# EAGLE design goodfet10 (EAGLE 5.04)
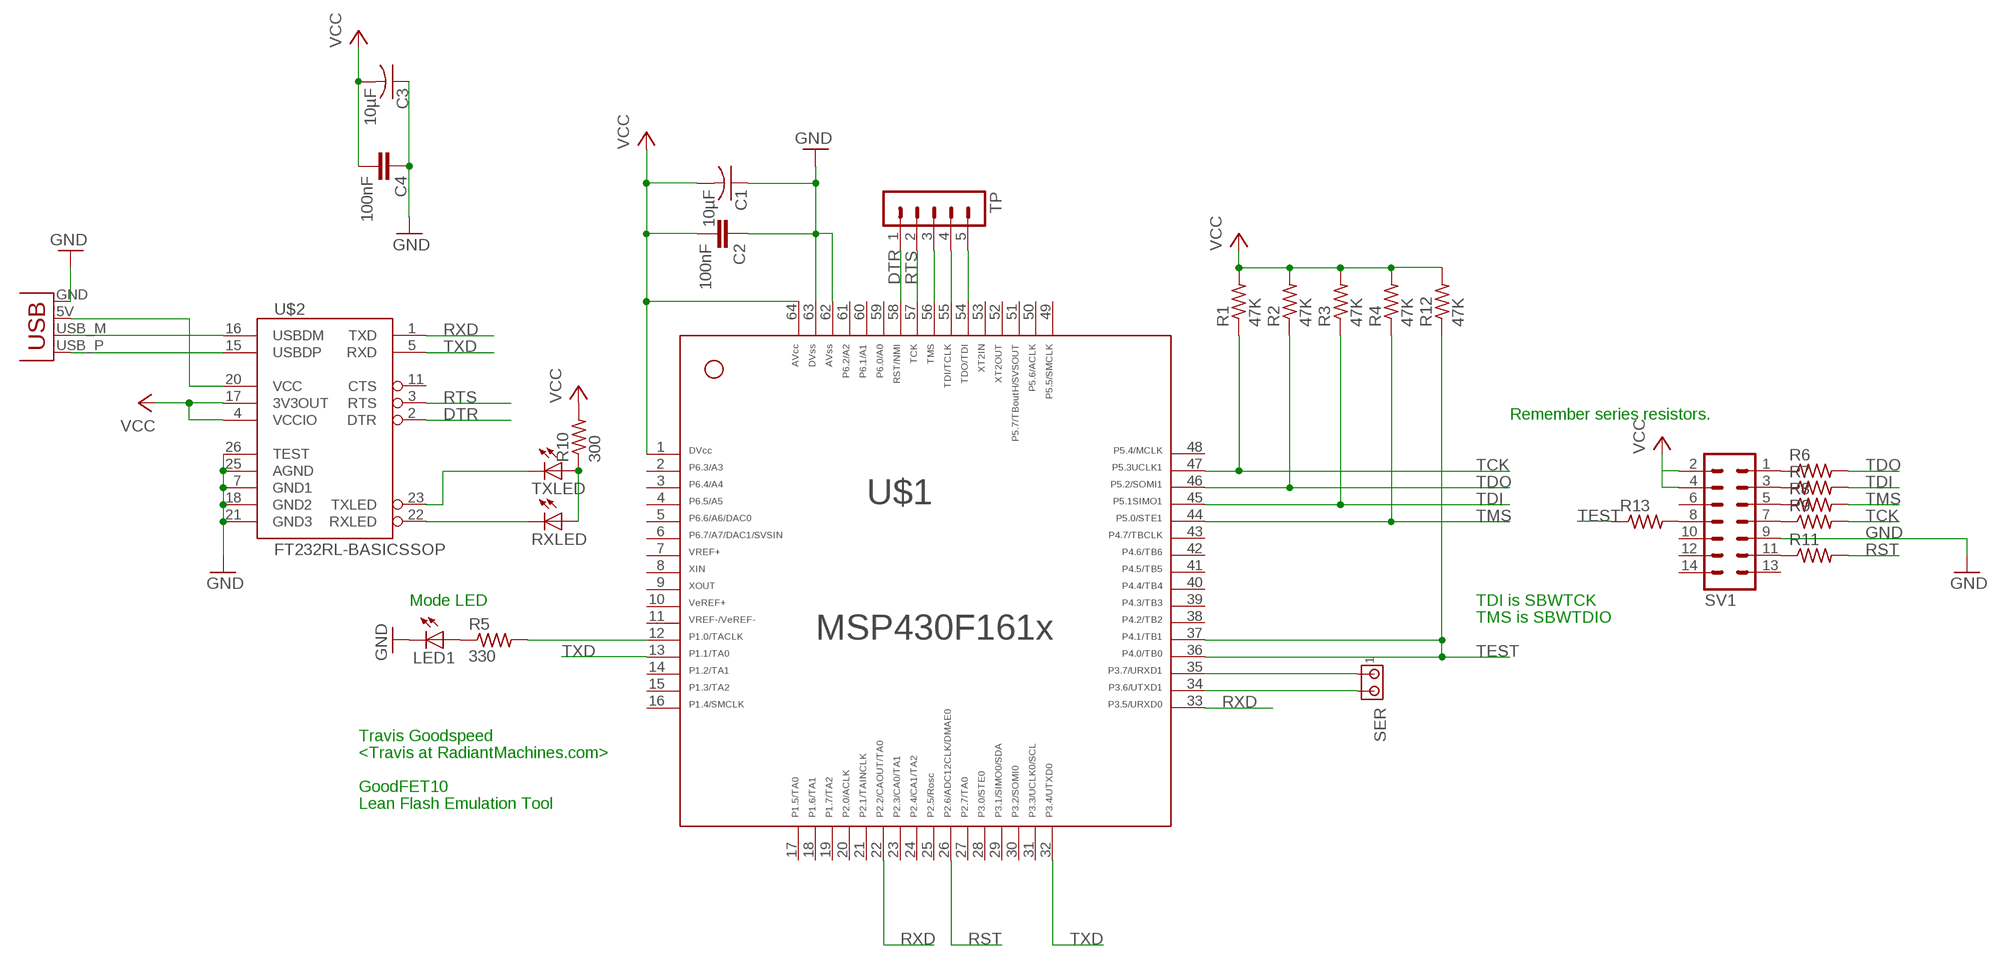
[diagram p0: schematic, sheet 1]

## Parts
C1  10µF  C-USC0603  [C0603]
C2  100nF  C-EUC0603  [C0603]
C3  10µF  C-USC0603  [C0603]
C4  100nF  C-EUC0603  [C0603]
LED1  LEDCHIP-LED0603  [CHIP-LED0603]
R1  47K  R-US_R0603  [R0603]
R2  47K  R-US_R0603  [R0603]
R3  47K  R-US_R0603  [R0603]
R4  47K  R-US_R0603  [R0603]
R5  330  R-US_R0603  [R0603]
R6  R-US_R0603  [R0603]
R7  R-US_R0603  [R0603]
R8  R-US_R0603  [R0603]
R9  R-US_R0603  [R0603]
R10  300  R-US_R0603  [R0603]
R11  R-US_R0603  [R0603]
R12  47K  R-US_R0603  [R0603]
R13  R-US_R0603  [R0603]
RXLED  LEDCHIP-LED0603  [CHIP-LED0603]
SER  MTA02-100  [10X02MTA]
SV1  MA07-2  [MA07-2]
TP  MA05-1  [MA05-1]
TXLED  LEDCHIP-LED0603  [CHIP-LED0603]
U$1  F161X---PM64  [PM/PAG64]
U$2  FT232RL-BASICSSOP  [SSOP28DB]
X1  USBPCB  [USB-A-PCB]

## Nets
DTR: TP.1 U$1.58 U$2.2(DTR)
GND: C1.1 C2.1 C3.1 C4.1 LED1.C SV1.9 U$1.62 U$1.63 U$2.7(GND1) U$2.18(GND2) U$2.21(GND3) U$2.25(AGND) U$2.26(TEST) X1.GND
N$1: R5.2 U$1.12
N$2: LED1.A R5.1
N$3: U$2.15(USBDP) X1.USB_P(D+)
N$4: U$2.16(USBDM) X1.USB_M(D-)
N$5: U$2.20(VCC) X1.5V(VBUS)
N$6: RXLED.C U$2.22(RXLED)
N$7: TXLED.C U$2.23(TXLED)
N$8: R10.1 RXLED.A TXLED.A
N$9: SER.1 U$1.35
N$10: SER.2 U$1.34
N$11: TP.3 U$1.56
N$12: TP.4 U$1.55
N$13: TP.5 U$1.54
N$14: R6.1 SV1.1
N$15: R7.1 SV1.3
N$16: R8.1 SV1.5
N$17: R9.1 SV1.7
N$18: R11.1 SV1.11
N$19: R13.2 SV1.8
RST: R11.2 U$1.26
RTS: TP.2 U$1.57 U$2.3(RTS)
RXD: U$1.22 U$1.33 U$2.1(TXD)
TCK: R1.1 R9.2 U$1.47
TDI: R3.1 R7.2 U$1.45
TDO: R2.1 R6.2 U$1.46
TEST: R12.1 R13.1 U$1.36 U$1.37
TMS: R4.1 R8.2 U$1.44
TXD: U$1.13 U$1.32 U$2.5(RXD)
VCC: C1.2 C2.2 C3.2 C4.2 R1.2 R2.2 R3.2 R4.2 R10.2 R12.2 SV1.2 SV1.4 U$1.1 U$1.64 U$2.4(VCCIO) U$2.17(3V3OUT)
Unconnected: SV1.6 SV1.10 SV1.12 SV1.13 SV1.14 U$1.2 U$1.3 U$1.4 U$1.5 U$1.6 U$1.7 U$1.8 U$1.9 U$1.10 U$1.11 U$1.14 U$1.15 U$1.16 U$1.17 U$1.18 U$1.19 U$1.20 U$1.21 U$1.23 U$1.24 U$1.25 U$1.27 U$1.28 U$1.29 U$1.30 U$1.31 U$1.38 U$1.39 U$1.40 U$1.41 U$1.42 U$1.43 U$1.48 U$1.49 U$1.50 U$1.51 U$1.52 U$1.53 U$1.59 U$1.60 U$1.61 U$2.11(CTS)

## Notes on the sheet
- Remember series resistors.
- Mode LED | TDI is SBWTCK
- TMS is SBWTDIO
- Travis Goodspeed
- <Travis at RadiantMachines.com>
- GoodFET10
- Lean Flash Emulation Tool

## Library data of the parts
C1 C3 = rcl:C-US: CAPACITOR, American symbol
C2 C4 = rcl:C-EU: CAPACITOR, European symbol
LED1 RXLED TXLED = led:LED: LED
R1-R5 R10 R12 = rcl:R-US_: RESISTOR, American symbol
R6-R9 R11 R13 = resistor:R-US_: RESISTOR, American symbol
SER = con-amp:MTA02-100: AMP connector
SV1 = con-lstb:MA07-2: PIN HEADER
TP = con-lstb:MA05-1: PIN HEADER
U$1 = TI_MSP430_v122:F161X---PM64: *** MSP430F161x *** PM64
U$2 = SparkFun:FT232RL-BASIC: USB UART This is the simplified version of the FT232RL unit. Only what you need, nothing you don't. Spark Fun Electronics SKU : COM-00650
X1 = SparkFun:USB: USB Connectors USB-B-PTH is fully proven SKU : PRT-00139 USB-miniB is fully proven SKU : PRT-00587 USB-A-PCB is untested. USB-A-H is throughly reviewed, but untested. Spark Fun Electronics SKU : PRT-00437 USB-B-SMT is throughly reviewed, but untested. Needs silkscreen touching up. USB-A-S has not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

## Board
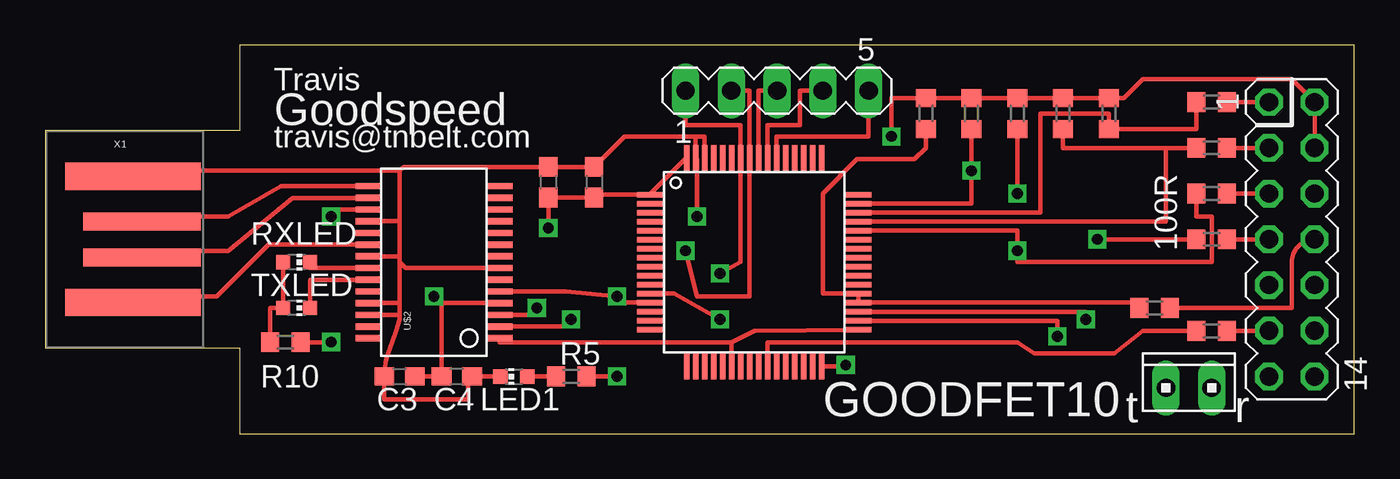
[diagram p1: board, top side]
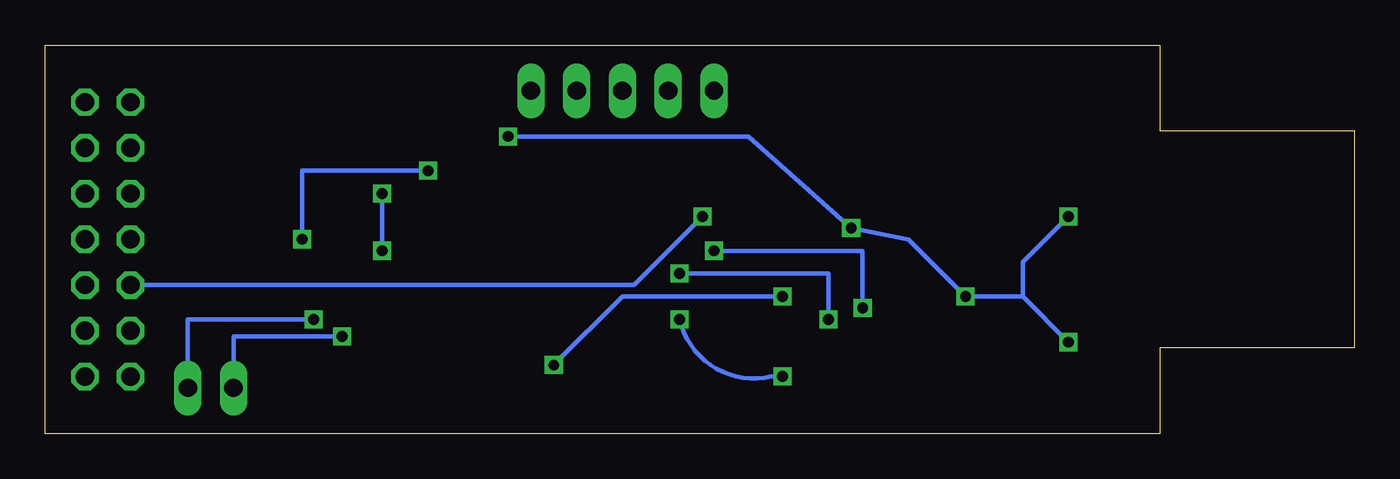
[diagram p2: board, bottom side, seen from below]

Size 72.69 x 21.59 mm. Coordinates in mm from the lower left corner, seen from the top.
Outline: 10.79,0 72.69,0 72.69,21.59 10.79,21.59 10.79,16.83 0,16.83 0,4.76 10.79,4.76 10.79,0
Copper layers (1*16): Top 0.035mm / dielectric 1.5mm / Bottom 0.035mm
Design rules "default": minimum track width 10mil, minimum drill 24mil, track to track 8mil, track to pad 8mil, pad to pad 8mil, via to via 8mil, smd to smd 8mil, copper to edge 40mil, drill to drill 8mil, minimum pad ring 10mil, minimum via ring 8mil, stop-mask expansion 4mil, vias tented up to drill 0mil, thermal gap 10mil

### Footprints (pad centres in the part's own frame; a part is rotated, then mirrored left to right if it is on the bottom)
C0603 = smd 1.1 x 1: 1 -0.85,0; 2 0.85,0
CHIP-LED0603 = smd 0.8 x 0.8: A 0,-0.75; C 0,0.75
R0603 = smd 1 x 1.1: 1 -0.85,0; 2 0.85,0
10X02MTA = drill 1.016 long: 1 1.27,0; 2 -1.27,0
MA07-2 = drill 1.016 octagon: 1 -7.62,-1.27; 2 -7.62,1.27; 3 -5.08,-1.27; 4 -5.08,1.27; 5 -2.54,-1.27; 6 -2.54,1.27; 7 0,-1.27; 8 0,1.27; 9 2.54,-1.27; 10 2.54,1.27; 11 5.08,-1.27; 12 5.08,1.27; 13 7.62,-1.27; 14 7.62,1.27
MA05-1 = drill 1.016 long: 1 -5.08,0; 2 -2.54,0; 3 0,0; 4 2.54,0; 5 5.08,0
PM/PAG64 = smd 1.4 x 0.3: 1 -5.8,3.75; 2 -5.8,3.25; 3 -5.8,2.75; 4 -5.8,2.25; 5 -5.8,1.75; 6 -5.8,1.25; 7 -5.8,0.75; 8 -5.8,0.25; 9 -5.8,-0.25; 10 -5.8,-0.75; 11 -5.8,-1.25; 12 -5.8,-1.75; 13 -5.8,-2.25; 14 -5.8,-2.75; 15 -5.8,-3.25; 16 -5.8,-3.75; 33 5.8,-3.75; 34 5.8,-3.25; 35 5.8,-2.75; 36 5.8,-2.25; 37 5.8,-1.75; 38 5.8,-1.25; 39 5.8,-0.75; 40 5.8,-0.25; 41 5.8,0.25; 42 5.8,0.75; 43 5.8,1.25; 44 5.8,1.75; 45 5.8,2.25; 46 5.8,2.75; 47 5.8,3.25; 48 5.8,3.75 | smd 0.3 x 1.4: 17 -3.75,-5.8; 18 -3.25,-5.8; 19 -2.75,-5.8; 20 -2.25,-5.8; 21 -1.75,-5.8; 22 -1.25,-5.8; 23 -0.75,-5.8; 24 -0.25,-5.8; 25 0.25,-5.8; 26 0.75,-5.8; 27 1.25,-5.8; 28 1.75,-5.8; 29 2.25,-5.8; 30 2.75,-5.8; 31 3.25,-5.8; 32 3.75,-5.8; 49 3.75,5.8; 50 3.25,5.8; 51 2.75,5.8; 52 2.25,5.8; 53 1.75,5.8; 54 1.25,5.8; 55 0.75,5.8; 56 0.25,5.8; 57 -0.25,5.8; 58 -0.75,5.8; 59 -1.25,5.8; 60 -1.75,5.8; 61 -2.25,5.8; 62 -2.75,5.8; 63 -3.25,5.8; 64 -3.75,5.8
SSOP28DB = smd 0.348 x 1.397: 1 -4.225,-3.656; 2 -3.575,-3.656; 3 -2.925,-3.656; 4 -2.275,-3.656; 5 -1.625,-3.656; 6 -0.975,-3.656; 7 -0.325,-3.656; 8 0.325,-3.656; 9 0.975,-3.656; 10 1.625,-3.656; 11 2.275,-3.656; 12 2.925,-3.656; 13 3.575,-3.656; 14 4.225,-3.656; 15 4.225,3.656; 16 3.575,3.656; 17 2.925,3.656; 18 2.275,3.656; 19 1.625,3.656; 20 0.975,3.656; 21 0.325,3.656; 22 -0.325,3.656; 23 -0.975,3.656; 24 -1.625,3.656; 25 -2.275,3.656; 26 -2.925,3.656; 27 -3.575,3.656; 28 -4.225,3.656
USB-A-PCB = smd 7.5 x 1.5: 5V -0.2,-3.5; GND -0.2,3.5 | smd 6.5 x 1: USB_M 0.3,-1; USB_P 0.3,1

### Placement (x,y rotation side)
C1  27.94,13.97 270 top
C2  30.48,13.97 270 top
C3  19.68,3.18 0 top
C4  22.86,3.18 180 top
LED1  26.04,3.18 90 top
R1  51.44,17.78 90 top
R2  59.05,17.78 90 top
R3  56.52,17.78 90 top
R4  53.98,17.78 90 top
R5  29.21,3.18 0 top
R6  64.77,18.42 180 top
R7  64.77,15.88 180 top
R8  64.77,13.33 180 top
R9  64.77,10.79 180 top
R10  13.33,5.08 0 top
R11  64.77,5.71 180 top
R12  48.9,17.78 90 top
R13  61.6,6.99 0 top
RXLED  13.97,9.53 270 top
SER  63.5,2.54 0 top
SV1  69.21,10.79 270 top
TP  40.64,19.05 0 top
TXLED  13.97,6.99 270 top
U$1  39.37,9.53 0 top
U$2  21.59,9.53 90 top
X1  5.08,10.79 0 top

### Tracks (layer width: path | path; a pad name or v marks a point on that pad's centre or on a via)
DTR  (via drill 0.6)
  Top 0.254: TP.1 35.56,17.14 38.62,17.14 U$1.58 38.62,9.53 v37.47,8.89 | U$2.2 29.21,5.95 v29.21,6.35
  Bottom 0.254: v29.21,6.35 29.21,8.89 v37.47,8.89
GND  (via drill 0.6)
  Top 0.254: 19.68,14.61 19.68,11.8 | 19.68,14.61 5.2,14.61 X1.GND | 19.68,11.8 U$2.18 | 19.68,11.8 19.68,10.16 | 19.68,10.16 19.68,9.53 | 19.68,9.53 19.68,7.62 | 19.68,7.62 19.68,6.6 | 19.68,6.6 U$2.26 | 19.68,6.6 19.68,6.35 arc-2 19.05,4.45 arc19 C3.1 18.83,1.91 23.49,1.91 23.49,3.18 C4.1 LED1.C | U$2.25 19.68,7.25 19.68,7.62 | U$2.21 19.68,9.85 19.68,10.16 | U$2.7 20.01,9.2 19.68,9.53 | 36.12,16.51 U$1.63 36.2,15.25 v36.2,12.07 | 36.12,16.51 32.17,16.51 C2.1 C1.1 19.9,14.82 19.68,14.61 | U$1.62 36.62,16.51 36.12,16.51
  Bottom 0.254: SV1.9 40.01,8.25 v36.2,12.07
N$1  (via drill 0.6)
  Top 0.254: R5.2 v31.75,3.18 | v37.47,6.35 34.93,7.78 U$1.12
  Bottom 0.254: v31.75,3.18 32.39,3.18 arc90 v37.47,6.35
N$2
  Top 0.254: LED1.A R5.1
N$3
  Top 0.254: U$2.15 13.11,13.75 10.16,12.07 5.65,12.07 X1.USB_P
N$4
  Top 0.254: U$2.16 13.73,13.1 10.16,10.16 5.75,10.16 X1.USB_M
N$5
  Top 0.254: U$2.20 12.4,10.5 9.52,7.62 5.2,7.62 X1.5V
N$6
  Top 0.254: U$2.22 14.72,9.2 RXLED.C
N$7
  Top 0.254: U$2.23 14.72,8.55 TXLED.C
N$8
  Top 0.254: RXLED.A TXLED.A 12.48,6.99 R10.1
N$9  (via drill 0.6)
  Top 0.254: U$1.35 57.79,6.78 v57.79,6.35
  Bottom 0.254: v57.79,6.35 64.77,6.35 SER.1
N$10  (via drill 0.6)
  Top 0.254: U$1.34 56.2,6.28 v56.2,5.4
  Bottom 0.254: v56.2,5.4 62.23,5.4 SER.2
N$11
  Top 0.254: U$1.56 39.62,19.05 TP.3
N$12
  Top 0.254: U$1.55 40.12,17.14 41.91,17.14 41.91,19.05 TP.4
N$13
  Top 0.254: U$1.54 40.62,16.51 45.72,16.51 TP.5
N$14
  Top 0.254: R6.1 SV1.1
N$15
  Top 0.254: R7.1 SV1.3
N$16
  Top 0.254: R8.1 SV1.5
N$17
  Top 0.254: R9.1 SV1.7
N$18
  Top 0.254: R11.1 SV1.11
N$19
  Top 0.254: R13.2 69.21,6.99 69.21,9.53 arc-90 SV1.8
RST
  Top 0.254: U$1.26 40.12,5.08 53.98,5.08 54.93,4.45 59.37,4.45 60.96,5.71 R11.2
RTS  (via drill 0.6)
  Top 0.254: TP.2 39.12,19.05 U$1.57 39.12,7.62 36.2,7.62 v35.56,10.16 | U$2.3 27.3,6.6 v27.3,6.99
  Bottom 0.254: v27.3,6.99 27.3,10.16 v35.56,10.16
RXD
  Top 0.254: U$2.1 25.25,5.08 38.1,5.08 | 38.1,5.08 39.4,5.71 U$1.33 | U$1.22 38.12,5.08 38.1,5.08
TCK  (via drill 0.6)
  Top 0.254: U$1.47 51.44,12.78 v51.44,14.61 R1.1 | 64.13,10.79 R9.2 v58.42,10.79
  Bottom 0.254: v58.42,10.79 58.42,14.61 v51.44,14.61
TDI
  Top 0.254: 62.23,15.88 56.52,15.88 R3.1 | 62.23,15.88 R7.2 | U$1.45 62.23,11.78 62.23,15.88
TDO
  Top 0.254: R6.2 63.92,16.93 R2.1 59.05,17.78 55.25,17.78 55.25,12.28 U$1.46
TEST
  Top 0.254: R13.1 60.74,7.28 U$1.36 U$1.37 43.18,7.78 43.18,13.33 45.09,15.24 48.26,15.24 48.9,15.88 R12.1
TMS  (via drill 0.6)
  Top 0.254: U$1.44 53.98,11.28 v53.98,10.16 53.98,9.53 64.77,9.53 64.77,12.07 63.92,12.07 R8.2 | v53.98,13.33 R4.1
  Bottom 0.254: v53.98,10.16 v53.98,13.33
TXD  (via drill 0.6)
  Top 0.254: U$1.32 44.37,3.72 v44.45,3.81 | U$2.5 28.93,7.9 v31.75,7.62 31.75,7.28 U$1.13
  Bottom 0.254: v44.45,3.81 40.64,7.62 v31.75,7.62
VCC  (via drill 0.6)
  Top 0.254: C3.2 C4.2 22.01,7.25 | 22.01,7.25 U$2.4 | R10.2 v15.88,5.08 | 22.01,7.25 21.96,7.25 v21.59,7.62 | v15.88,12.07 16.26,12.45 U$2.17 | U$1.64 U$1.1 30.48,13.28 C2.2 C1.2 v27.94,11.43 | SV1.4 SV1.2 69.21,19.68 60.96,19.68 59.91,18.63 R2.2 R3.2 R4.2 R1.2 R12.2 46.99,18.63 v46.99,16.51
  Bottom 0.254: 18.41,7.62 v21.59,7.62 24.76,10.79 v27.94,11.43 33.66,16.51 v46.99,16.51 | v15.88,5.08 18.41,7.62 | 18.41,7.62 18.41,9.53 v15.88,12.07

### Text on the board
tPlace: Travis | Goodspeed | travis@tnbelt.com | 100R | GOODFET10
tNames: t | r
